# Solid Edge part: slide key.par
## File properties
Title: Slide Key
Author: Deepak Maini
Template: Normal.par
Last saved by: Robert a Rhodes jr
Revision: 7
Application: Solid Edge
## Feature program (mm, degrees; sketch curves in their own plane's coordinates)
sketch for "unnamed Protrusion 1" plane through (0, 0, 0) normal (0, -1, 0) x-axis (1, 0, 0)
  line (-30.0365, -12.1146) -> (28.6883, -12.1146)
  line (28.6883, -12.1146) -> (28.6883, -17.6629)
  line (1.9812, -17.6629) -> (28.6883, -17.6629)
  line (1.9812, -13.3979) -> (1.9812, -17.6629)
  line (-1.9812, -13.3979) -> (1.9812, -13.3979)
  line (-1.9812, -17.6629) -> (-1.9812, -13.3979)
  line (-30.0365, -17.6629) -> (-1.9812, -17.6629)
  line (-30.0365, -17.6629) -> (-30.0365, -12.1146)
extrude "unnamed Protrusion 1" add finite 4.7244 along +normal
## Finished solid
Body 1: solid body, 10 faces, 24 edges, 16 vertices.
  Faces by surface: plane 10
  Edges by curve: line 24
Bounding box of the edges (mm): 58.725 x 4.724 x 5.548, from (-30.0365, -4.7244, -17.6629) to (28.6883, 0, -12.1146).
Planar faces by outward normal: +x 2, +y 1, +z 1, -x 2, -y 1, -z 3
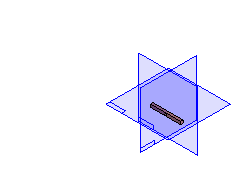
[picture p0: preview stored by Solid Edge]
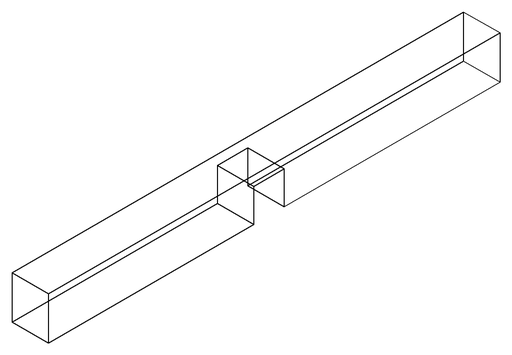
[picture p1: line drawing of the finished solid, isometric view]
